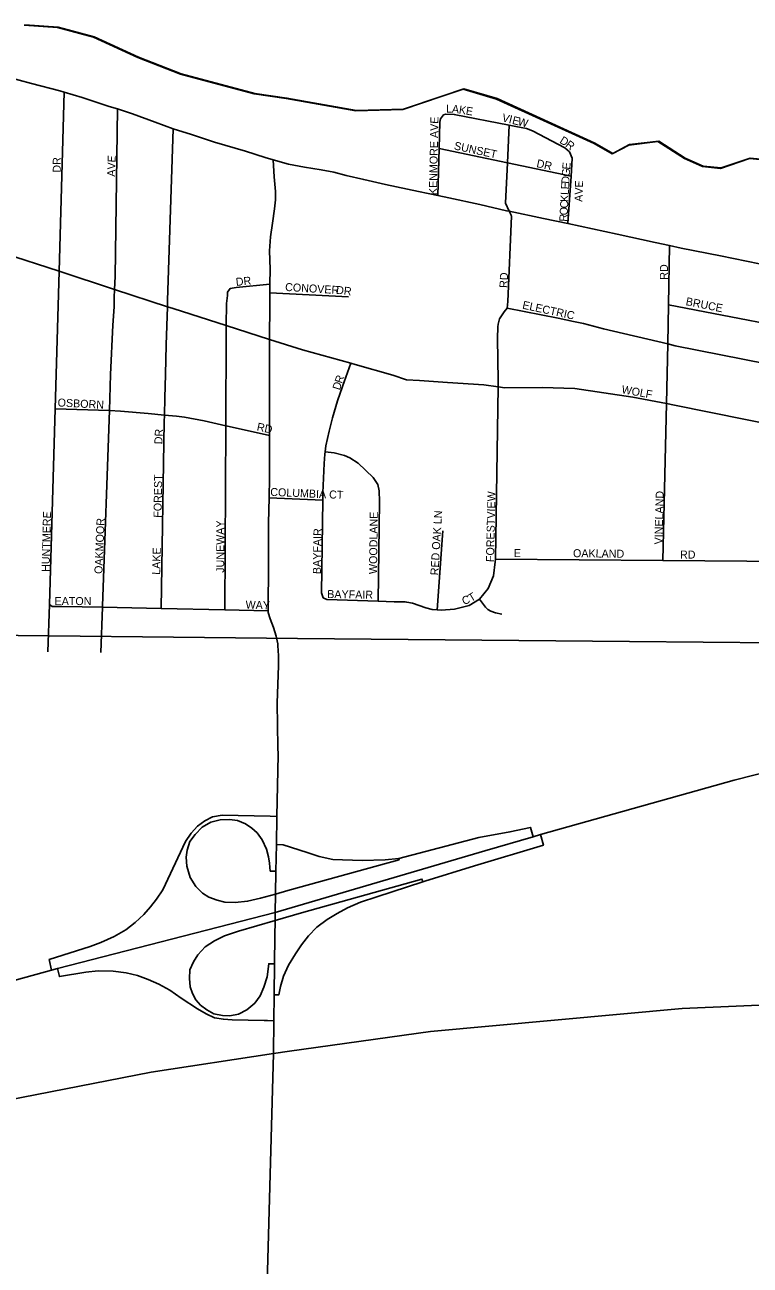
# Model space of a CAD drawing. Extents: x -561 to 1170, y 0 to 846.
# Drawn here: x 84.16 to 96.4, y 255.36 to 276.28 of the extents above; entities that cross this region are included whole.
import ezdxf

# ---------------------------------------------------------------- set-up
doc = ezdxf.new("R2010")
doc.units = 0
for name, color, linetype in [('GM_X_City_Street', 7, 'Continuous'), ('GM_X_City_Street_Text', 7, 'Continuous'), ('GM_X_County', 7, 'Continuous'), ('GM_X_Interchange_Ramps', 7, 'Continuous'), ('GM_X_Interstate_Route', 7, 'Continuous'), ('GM_X_Major_Lake', 7, 'Continuous'), ('GM_X_Major_River', 7, 'Continuous'), ('GM_X_Rail_Line', 7, 'Continuous'), ('GM_X_State_Route', 7, 'Continuous'), ('GM_X_US_Route', 7, 'Continuous')]:
    doc.layers.add(name, color=color, linetype=linetype)

msp = doc.modelspace()

# ---------------------------------------------------------------- linework, layer by layer
at = {"layer": 'GM_X_City_Street'}
for points in [[(84.553, 265.698), (84.578, 266.496), (84.674, 269.801), (84.741, 272.118), (84.83, 275.138)], [(85.447, 265.69), (85.475, 266.451), (85.477, 266.478), (85.59, 269.773), (85.611, 270.375), (85.646, 271.209), (85.67, 271.518), (85.674, 271.676), (85.679, 271.812), (85.687, 272.028), (85.729, 274.856)], [(91.132, 273.395), (91.153, 274.187), (91.166, 274.636), (91.176, 274.69), (91.224, 274.756)], [(91.224, 274.756), (91.267, 274.767), (91.408, 274.763), (92.333, 274.584), (92.444, 274.563), (92.628, 274.527), (92.726, 274.49), (93.275, 274.203), (93.352, 274.133)], [(86.462, 266.431), (86.517, 269.582), (86.519, 269.693), (86.524, 269.983), (86.537, 270.379), (86.548, 270.877), (86.57, 271.521), (86.573, 271.625), (86.664, 274.522)], [(92.366, 273.062), (92.366, 273.063), (92.335, 273.13), (92.272, 273.266), (92.304, 273.947), (92.333, 274.584)], [(91.153, 274.187), (92.304, 273.947), (93.38, 273.722)], [(93.324, 272.923), (93.38, 273.722), (93.387, 273.819), (93.396, 274.025), (93.352, 274.133)], [(92.099, 267.218), (92.099, 267.219), (92.104, 267.262), (92.149, 270.17), (92.15, 270.274), (92.138, 270.984), (92.142, 271.179), (92.146, 271.228), (92.173, 271.315), (92.247, 271.435), (92.301, 271.495), (92.31, 271.609), (92.372, 273.05), (92.366, 273.062)], [(83.805, 272.424), (84.741, 272.118), (85.679, 271.812), (86.57, 271.521), (86.664, 271.491), (87.559, 271.203), (88.292, 270.967), (88.847, 270.795), (89.664, 270.568), (89.738, 270.547), (90.371, 270.369), (90.603, 270.288), (90.819, 270.278), (91.294, 270.24), (91.905, 270.203), (92.149, 270.17), (92.261, 270.155), (92.888, 270.161), (93.439, 270.14), (94.417, 269.995), (94.985, 269.887), (95.125, 269.86), (96.93, 269.494)], [(94.925, 267.239), (94.985, 269.887), (95.008, 270.893), (95.023, 271.555), (95.04, 272.552)], [(87.539, 266.408), (87.552, 269.514), (87.558, 271.088), (87.559, 271.203), (87.564, 271.576), (87.584, 271.712), (87.584, 271.766), (87.627, 271.826), (87.729, 271.843), (88.299, 271.903)], [(88.297, 271.757), (89.625, 271.689)], [(95.023, 271.555), (97.885, 271.001), (97.946, 270.99), (99.828, 270.603), (101.308, 270.299), (101.367, 270.289), (101.558, 270.258), (102.856, 270.076)], [(92.301, 271.495), (93.163, 271.325), (93.418, 271.273), (93.586, 271.237), (93.923, 271.149), (95.008, 270.893), (95.132, 270.863), (97.844, 270.326)], [(89.194, 266.609), (89.166, 266.695), (89.19, 268.261), (89.192, 268.38), (89.214, 268.879), (89.224, 269.036), (89.229, 269.075), (89.244, 269.177), (89.296, 269.421), (89.353, 269.649), (89.437, 269.932), (89.521, 270.177), (89.664, 270.568)], [(84.674, 269.801), (85.59, 269.773), (85.776, 269.759), (86.245, 269.72), (86.519, 269.693), (86.722, 269.674), (86.858, 269.656), (87.188, 269.595), (87.552, 269.514), (87.563, 269.512), (88.291, 269.348)], [(90.125, 266.554), (90.146, 268.238), (90.139, 268.417), (90.116, 268.525), (90.039, 268.643), (89.788, 268.885), (89.647, 268.97), (89.554, 269.012), (89.38, 269.054), (89.229, 269.075)], [(88.284, 268.295), (89.19, 268.261)], [(91.118, 266.408), (91.217, 267.74)], [(91.835, 266.587), (91.979, 266.767), (92.069, 266.98), (92.099, 267.218)], [(92.104, 267.262), (94.925, 267.239), (97.758, 267.216), (101.327, 267.187), (102.575, 267.176)], [(89.194, 266.609), (89.259, 266.582), (90.125, 266.554), (90.396, 266.545), (90.58, 266.542), (90.607, 266.537), (90.61, 266.537)], [(90.61, 266.537), (90.704, 266.521), (90.927, 266.442), (91.036, 266.416), (91.118, 266.408), (91.187, 266.402), (91.409, 266.42), (91.657, 266.482), (91.835, 266.587)], [(91.835, 266.587), (91.937, 266.453), (91.976, 266.416), (92.027, 266.384), (92.102, 266.357), (92.209, 266.334)], [(84.578, 266.496), (84.627, 266.464), (84.789, 266.465), (85.475, 266.451), (86.462, 266.431), (87.539, 266.408), (88.269, 266.393)]]:
    msp.add_lwpolyline(points, dxfattribs=at)
at = {"layer": 'GM_X_County'}
msp.add_lwpolyline([(84.151, 276.268), (84.714, 276.228), (85.322, 276.068), (86.071, 275.725), (86.788, 275.441), (88.03, 275.111), (88.572, 275.033), (89.749, 274.822), (90.54, 274.847), (91.189, 275.067), (91.557, 275.188), (92.121, 275.023), (93.766, 274.272), (94.071, 274.1), (94.352, 274.248), (94.844, 274.305), (95.29, 274.02), (95.594, 273.886), (95.898, 273.854), (96.39, 274.019), (97.214, 273.942)], dxfattribs=at)
at = {"layer": 'GM_X_Interchange_Ramps'}
for points in [[(88.417, 262.926), (88.304, 262.93), (87.495, 262.945), (87.331, 262.916), (87.2, 262.851), (87.079, 262.759), (86.972, 262.644), (86.872, 262.502), (86.494, 261.689), (86.384, 261.529), (86.284, 261.401), (86.17, 261.27), (86.026, 261.138), (85.866, 261.013), (85.673, 260.898), (85.447, 260.797), (85.264, 260.729), (84.575, 260.511), (84.617, 260.332)], [(90.471, 262.214), (90.476, 262.195), (90.295, 262.144), (88.602, 261.676), (88.393, 261.616), (88.138, 261.544), (87.921, 261.493), (87.71, 261.474), (87.537, 261.48), (87.409, 261.513), (87.269, 261.565), (87.161, 261.633), (87.049, 261.744), (86.952, 261.897), (86.897, 262.087), (86.884, 262.237), (86.9, 262.357), (86.946, 262.503), (87.038, 262.621), (87.158, 262.743), (87.3, 262.825), (87.46, 262.868), (87.618, 262.873), (87.751, 262.853), (87.884, 262.799), (87.993, 262.728), (88.086, 262.645), (88.169, 262.529), (88.241, 262.373), (88.276, 262.241), (88.293, 262.135), (88.303, 262.002), (88.4, 262)], [(88.369, 259.916), (88.448, 259.913), (88.478, 260.055), (88.526, 260.23), (88.613, 260.415), (88.727, 260.605), (88.83, 260.757), (88.949, 260.908), (89.09, 261.059), (89.263, 261.187), (89.43, 261.288), (89.608, 261.383), (89.825, 261.477), (90.102, 261.57), (90.877, 261.822), (90.911, 261.833), (91.748, 262.089), (92.912, 262.441), (92.864, 262.618)], [(92.738, 262.582), (92.696, 262.738), (92.346, 262.664), (91.82, 262.568), (90.471, 262.214), (90.242, 262.193), (89.854, 262.179), (89.36, 262.199), (89.131, 262.25), (88.927, 262.315), (88.519, 262.447), (88.408, 262.45)], [(88.376, 260.437), (88.278, 260.439), (88.251, 260.22), (88.198, 260.045), (88.134, 259.898), (88.043, 259.773), (87.908, 259.661), (87.769, 259.592), (87.62, 259.562), (87.499, 259.565), (87.351, 259.596), (87.232, 259.665), (87.129, 259.744), (87.049, 259.834), (86.991, 259.94), (86.955, 260.051), (86.941, 260.189), (86.95, 260.337), (87.008, 260.473), (87.082, 260.593), (87.206, 260.727), (87.363, 260.828), (87.53, 260.913), (87.768, 260.99), (88.385, 261.168), (88.831, 261.296), (90.863, 261.867), (90.877, 261.822)], [(84.714, 260.357), (84.748, 260.223), (85.194, 260.299), (85.404, 260.322), (85.657, 260.316), (85.876, 260.284), (86.062, 260.241), (86.242, 260.177), (86.427, 260.096), (86.612, 259.992), (86.802, 259.862), (87.078, 259.679), (87.225, 259.593), (87.361, 259.53), (87.514, 259.504), (87.663, 259.496), (88.201, 259.483), (88.256, 259.482), (88.363, 259.478)]]:
    msp.add_lwpolyline(points, dxfattribs=at)
at = {"layer": 'GM_X_Interstate_Route'}
for points in [[(91.922, 262.343), (92.738, 262.582), (92.864, 262.618), (96.127, 263.534), (97.102, 263.784), (98.861, 264.138), (100.129, 264.344), (101.1, 264.459), (101.771, 264.539), (102.06, 264.569)], [(88.387, 261.305), (91.922, 262.343)], [(64.426, 255.878), (65.596, 255.782), (66.869, 255.743), (67.705, 255.821), (68.388, 255.931), (69.108, 256.086), (73.71, 257.355), (76.118, 257.989), (84.617, 260.332), (84.714, 260.357), (88.387, 261.305)]]:
    msp.add_lwpolyline(points, dxfattribs=at)
at = {"layer": 'GM_X_Major_Lake'}
for points in [[(84.162, 276.275), (84.726, 276.235), (85.333, 276.075), (86.083, 275.732), (86.799, 275.448), (88.042, 275.118), (88.584, 275.04), (89.76, 274.829), (90.551, 274.854), (91.201, 275.074), (91.568, 275.195), (92.133, 275.03), (93.778, 274.279), (94.082, 274.107), (94.363, 274.255), (94.856, 274.311), (95.302, 274.026), (95.606, 273.892), (95.909, 273.861)], [(84.162, 276.275), (84.726, 276.235), (85.333, 276.075), (86.083, 275.732), (86.799, 275.448), (88.042, 275.118), (88.584, 275.04), (89.76, 274.829), (90.551, 274.854), (91.201, 275.074), (91.568, 275.195), (92.133, 275.03), (93.778, 274.279), (94.082, 274.107), (94.363, 274.255), (94.856, 274.311), (95.302, 274.026), (95.606, 273.892), (95.909, 273.861)], [(95.909, 273.861), (96.401, 274.026), (97.225, 273.949), (97.578, 273.848), (98.463, 273.549), (98.946, 273.377), (99.335, 273.428), (99.775, 273.289), (100.333, 273.238), (100.892, 273.067), (101.548, 273.097), (102.6, 272.81), (103.3, 272.564), (103.918, 272.426), (104.428, 272.374), (105.003, 272.263), (105.475, 272.168), (105.837, 272.23), (106.342, 272.059), (106.884, 272.007), (107.345, 271.912), (108.055, 271.883)]]:
    msp.add_lwpolyline(points, dxfattribs=at)
at = {"layer": 'GM_X_Major_River'}
for points in [[(84.162, 276.275), (84.726, 276.235), (85.333, 276.075), (86.083, 275.732), (86.799, 275.448), (88.042, 275.118), (88.584, 275.04), (89.76, 274.829), (90.551, 274.854), (91.201, 275.074), (91.568, 275.195), (92.133, 275.03), (93.778, 274.279), (94.082, 274.107), (94.363, 274.255), (94.856, 274.311), (95.302, 274.026), (95.606, 273.892), (95.909, 273.861)], [(95.909, 273.861), (96.401, 274.026), (97.225, 273.949), (97.578, 273.848), (98.463, 273.549), (98.946, 273.377), (99.335, 273.428), (99.775, 273.289), (100.333, 273.238), (100.892, 273.067), (101.548, 273.097), (102.6, 272.81), (103.3, 272.564), (103.918, 272.426), (104.428, 272.374), (105.003, 272.263), (105.475, 272.168), (105.837, 272.23), (106.342, 272.059), (106.884, 272.007), (107.345, 271.912), (108.055, 271.883)]]:
    msp.add_lwpolyline(points, dxfattribs=at)
at = {"layer": 'GM_X_Rail_Line'}
msp.add_lwpolyline([(82.475, 265.99), (88.766, 265.928), (94.366, 265.876), (108.03, 265.751), (117.97, 265.658), (118.268, 265.664), (118.487, 265.676), (118.734, 265.691), (118.933, 265.71), (119.151, 265.735), (119.394, 265.772), (119.618, 265.814), (119.861, 265.868), (120.32, 265.986), (120.567, 266.065), (120.872, 266.171), (121.159, 266.285), (121.657, 266.478), (124.688, 267.682), (130.977, 270.172)], dxfattribs=at)
at = {"layer": 'GM_X_State_Route'}
for points in [[(88.442, 265.665), (88.44, 265.69), (88.431, 265.835), (88.404, 265.965), (88.356, 266.111), (88.301, 266.257), (88.269, 266.365), (88.269, 266.393), (88.269, 266.511), (88.275, 267.079), (88.275, 267.875), (88.284, 268.295), (88.291, 268.633), (88.291, 269.348), (88.291, 269.547), (88.292, 270.424), (88.292, 270.967), (88.292, 271.068), (88.297, 271.468), (88.297, 271.757), (88.297, 271.826), (88.299, 271.903), (88.303, 272.156), (88.292, 272.464), (88.308, 272.702), (88.341, 272.93), (88.373, 273.173), (88.395, 273.325), (88.39, 273.465), (88.368, 273.714), (88.352, 273.996)], [(88.417, 262.926), (88.436, 263.963), (88.431, 264.092), (88.42, 264.833), (88.442, 265.472), (88.442, 265.661), (88.442, 265.665)], [(88.382, 260.906), (88.385, 261.168), (88.387, 261.305), (88.393, 261.616), (88.4, 262), (88.408, 262.45), (88.417, 262.926)], [(88.356, 258.927), (88.363, 259.478), (88.369, 259.916), (88.376, 260.437), (88.382, 260.906)], [(88.626, 258.965), (91.008, 259.296), (95.252, 259.683), (97.071, 259.763), (98.052, 259.879), (98.413, 259.963), (98.781, 260.065), (99.339, 260.205), (99.44, 260.228)], [(80.967, 257.57), (86.293, 258.609), (88.356, 258.927), (88.626, 258.965)], [(88.145, 250.96), (88.158, 251.582), (88.356, 258.927)]]:
    msp.add_lwpolyline(points, dxfattribs=at)
at = {"layer": 'GM_X_US_Route'}
for points in [[(83.859, 275.399), (84.279, 275.285), (84.755, 275.16), (84.83, 275.138), (85.134, 275.047), (85.588, 274.9), (85.729, 274.856), (85.983, 274.776), (86.361, 274.635), (86.664, 274.522), (86.681, 274.516), (86.956, 274.429), (87.362, 274.294), (87.887, 274.142), (88.219, 274.038), (88.352, 273.996)], [(88.352, 273.996), (88.611, 273.925), (88.882, 273.877), (89.163, 273.828), (89.374, 273.79), (89.585, 273.736), (89.882, 273.665), (90.25, 273.584), (90.802, 273.465), (91.132, 273.395), (91.316, 273.356), (91.84, 273.243), (92.289, 273.14), (92.335, 273.13), (92.911, 273.01), (93.324, 272.923), (93.533, 272.879), (94.155, 272.744), (94.799, 272.603), (95.04, 272.552), (95.237, 272.511), (95.897, 272.381), (96.557, 272.245)]]:
    msp.add_lwpolyline(points, dxfattribs=at)

# ---------------------------------------------------------------- texts
at = {"layer": 'GM_X_City_Street_Text'}
for s, rotation, p in [('L', 359.4262, (91.271, 274.794)), ('A', 354.3079, (91.363, 274.793)), ('K', 351.0461, (91.479, 274.781)), ('E', 350.9194, (91.596, 274.763)), ('KENMORE AVE', 88.8648, (91.115, 273.402)), ('V', 346.0486, (92.203, 274.65)), ('I', 346.0092, (92.319, 274.622)), ('E', 346.049, (92.376, 274.607)), ('W', 346.0412, (92.469, 274.585)), ('SUNSET', 347.827, (91.395, 274.175)), ('D', 328.0016, (93.173, 274.291)), ('R', 323.1228, (93.271, 274.23)), ('AVE', 88.0261, (85.686, 273.712)), ('DR', 90, (84.771, 273.782)), ('DR', 347.4776, (92.786, 273.878)), ('G', 86.4455, (93.355, 273.711)), ('E', 85.1592, (93.362, 273.829)), ('D', 86.8685, (93.348, 273.592)), ('AVE', 88.0223, (93.569, 273.288)), ('L', 86.8605, (93.338, 273.403)), ('E', 86.8605, (93.343, 273.498)), ('C', 86.8538, (93.325, 273.177)), ('K', 86.8515, (93.331, 273.284)), ('R', 86.8538, (93.313, 272.952)), ('O', 86.857, (93.319, 273.059)), ('RD', 90, (95.012, 271.976)), ('DR', 5.7073, (87.729, 271.871)), ('RD', 86.9833, (92.303, 271.835)), ('CONOVER', 356.582, (88.552, 271.788)), ('DR', 353.6638, (89.409, 271.74)), ('ELECTRIC', 347.8452, (92.548, 271.49)), ('BRUCE', 348.6915, (95.304, 271.55)), ('R', 70.4589, (89.513, 270.217)), ('D', 72.6329, (89.478, 270.105)), ('WOLF', 349.5626, (94.222, 270.065)), ('OSBORN', 356.9352, (84.715, 269.84)), ('DR', 86.989, (86.482, 269.198)), ('RD', 348.1171, (88.069, 269.435)), ('FOREST', 89.0765, (86.47, 267.961)), ('COLUMBIA CT', 357.5903, (88.302, 268.331)), ('FORESTVIEW', 88.7134, (92.077, 267.213)), ('VINELAND', 88.4098, (94.917, 267.51)), ('HUNTMERE', 88.5115, (84.581, 267.047)), ('WOODLANE', 89.2842, (90.105, 267.011)), ('RED OAK LN', 86.5532, (91.139, 266.988)), ('OAKMOOR', 87.6154, (85.472, 267.012)), ('JUNEWAY', 90, (87.527, 267.034)), ('BAYFAIR', 89.0613, (89.157, 267.011)), ('LAKE', 88.4498, (86.446, 266.999)), ('E', 0, (92.412, 267.297)), ('OAKLAND', 359.2724, (93.41, 267.297)), ('RD', 0, (95.215, 267.273)), ('BAYFAIR', 359.0765, (89.264, 266.608)), ('EATON', 0, (84.666, 266.489)), ('WAY', 358.211, (87.886, 266.43)), ('C', 19.3067, (91.565, 266.49)), ('T', 30.7474, (91.693, 266.537))]:
    msp.add_text(s, height=0.135, rotation=rotation, dxfattribs=at).set_placement(p)

doc.saveas('drawing.dxf')
